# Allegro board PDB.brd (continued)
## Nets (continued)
GND: C1.2(B) C2.2(B) C3.2(B) C4.2(B) C5.2(B) C6.2(B) C7.2(B) C8.2(B) C9.2(B) C10.2(B) C11.2(B) C12.2(B) C13.2(B) C14.2(B) C15.2(B) C16.2(B) C17.2(B) C18.2(B) C19.2(B) C20.2(B) C21.2(B) C22.2(B) C23.2(B) C24.2(B) C25.2(B) C26.2(B) C27.2(B) C28.2(B) C29.2(B) C30.2(B) C31.2(B) C32.2(B) C33.2(B) C34.2(B) C35.2(B) C36.2(B) C39.2(B) C40.2(B) C41.2(B) C42.2(B) C43.1 C44.1 C45.2(B) C46.2(B) C47.2(B) C48.2(B) C49.2(B) C50.2(B) C51.2(B) C52.2(B) C53.1 C54.1 C55.2(B) C56.2(B) C57.2(B) C58.2(B) C59.2(B) C60.2(B) C61.2(B) C62.2(B) C63.2(B) C64.2(B) C65.2(B) C66.2(B) C67.2(B) C68.2(B) C69.2(B) C70.2(B) C71.2(B) C72.2(B) C73.2(B) C74.2(B) C75.2(B) C76.2(B) C77.2(B) C78.2(B) C79.2(B) C80.2(B) C81.2(B) C82.2(B) C83.2(B) C84.2(B) C85.2(B) C86.2(B) C87.2(B) C88.2(B) C89.2(B) C90.2(B) C91.2(B) C92.2(B) C97.2(B) C98.2(B) C99.2(B) C100.2(B) C101.2(B) C102.2(B) C103.2(B) C104.2(B) C105.2(B) C108.2(B) C109.2(B) C114.2(B) C115.2(B) C116.2(B) C117.2(B) C118.2(B) C119.2(B) C120.2(B) C121.2(B) C122.2(B) C123.2(B) C124.2(B) C125.2(B) C126.2(B) C127.2(B) C128.2(B) C129.2(B) C130.2(B) C131.2(B) C132.2(B) C133.2(B) C134.2(B) C135.2(B) C136.2(B) C137.2(B) C138.2(B) C139.2(B) C140.2(B) C141.2(B) C142.2(B) C143.2(B) C144.2(B) C145.2(B) C146.2(B) C147.2(B) C148.2(B) C149.2(B) C150.2(B) C151.2(B) C152.2(B) C153.2(B) C154.2(B) C155.2(B) C156.2(B) C157.2(B) C158.2(B) C159.2(B) C160.2(B) C161.2(B) C162.2(B) C163.2(B) C164.2(B) C165.2(B) C166.2(B) C167.2(B) C168.2(B) C170.2(B) C171.2(B) C172.2(B) C174.2(B) C175.2(B) C176.2(B) C178.2(B) C191.2(B) C192.2(B) C193.2(B) D7.1 D7.2 D8.1 D8.2 D9.1 D9.2 D10.1 D10.2 D11.2 J1.7 J1.8 J1.9 J1.10 J1.11 J1.12 J1.19 J1.20 J1.21 J1.22 J1.23 J1.24 J2.7 J2.8 J2.9 J2.10 J2.11 J2.12 J2.19 J2.20 J2.21 J2.22 J2.23 J2.24 J3.7 J3.8 J3.9 J3.10 J3.11 J3.12 J3.19 J3.20 J3.21 J3.22 J3.23 J3.24 J4.7 J4.8 J4.9 J4.10 J4.11 J4.12 J4.19 J4.20 J4.21 J4.22 J4.23 J4.24 J5.9 J6.9 J7.9 J8.9 J9.3 J9.8 J10.2 J11.1 J11.2 J11.3 J11.4 J11.5 J11.6 J11.13 J11.14(GND2) J12.2 J12.3 J12.6 J12.7 J13.1 J13.2 J13.3 J13.4 J13.9 J13.10 J13.11 J13.12 J13.17 J13.18(GND2) J14.1 J14.2 J14.3 J14.4 J14.9 J14.10 J14.11 J14.12 J14.17 J14.18(GND2) J15.1 J15.2 J15.3 J15.4 J15.9 J15.10 J15.11 J15.12 J15.17 J15.18(GND2) J16.7 J16.8 J16.9 J16.10 J16.11 J16.12 J16.13 J16.14(GND2) J17.7 J17.8 J17.9 J17.10 J17.11 J17.12 J17.13 J17.14(GND2) J18.7 J18.8 J18.9 J18.10 J18.11 J18.12 J18.13 J18.14(GND2) J19.1 J19.3 J19.5 J19.6(GND2) J20.2 MH1.2 MH1.3 MH1.4 MH1.5 MH1.6 MH2.2 MH2.3 MH2.4 MH2.5 MH2.6 MH3.2 MH3.3 MH3.4 MH3.5 MH3.6 MH4.2 MH4.3 MH4.4 MH4.5 MH4.6 MH5.2 MH5.3 MH5.4 MH5.5 MH5.6 MH6.1 MH7.1 PC29.2(B) PC30.2(B) PC31.2(B) PC32.2(B) PC33.2(B) PC34.2(B) PC101.2(B) PC102.2(B) PC103.2(B) PC104.2(B) PC105.2(B) PC106.2(B) PC107.2(B) PC108.2(B) PC819.2(B) PC820.2(B) PC822.2(B) PC824.2(B) PC825.2(B) PC827.2(B) PC830.2(B) PC832.2(B) PC833.2(B) PC834.2(B) PC835.2(B) PC836.2(B) PC837.2(B) PC838.2(B) PC840.2(B) PC841.2(B) PC843.2(B) PC844.2(B) PC845.2(B) PC846.2(B) PC847.2(B) PC848.2(B) PC849.2(B) PC850.2(B) PC851.2(B) PC1021.1 PC1022.2(B) PC1024.2(B) PC1819.2(B) PC1820.2(B) PC1822.2(B) PC1824.2(B) PC1825.2(B) PC1827.2(B) PC1830.2(B) PC1832.2(B) PC1833.2(B) PC1834.2(B) PC1835.2(B) PC1836.2(B) PC1837.2(B) PC1838.2(B) PC1840.2(B) PC1841.2(B) PC1843.2(B) PC1844.2(B) PC1845.2(B) PC1846.2(B) PC1847.2(B) PC1848.2(B) PC1849.2(B) PC1850.2(B) PC1851.2(B) PD1.2 PQ2.1 PQ2.4 PR24.2(B) PR707.2(B) PR1040.2(B) PR1046.1 PR1707.2(B) PU12.23 PU33.11 PU113.11 Q1.1 Q1.4 Q2.1 Q2.4 Q3.S Q4.S Q13.1 Q13.4 Q14.1 Q14.4 Q15.1 Q15.4 Q16.1 Q16.4 Q17.1 Q17.4 Q18.1 Q18.4 Q19.1 Q19.4 Q20.1 Q20.4 Q21.1 Q21.4 Q22.1 Q22.4 R17.2(B) R18.2(B) R19.2(B) R20.2(B) R26.2(B) R27.2(B) R28.2(B) R29.2(B) R30.2(B) R31.2(B) R32.2(B) R33.2(B) R34.2(B) R35.2(B) R47.2(B) R61.2(B) R78.2(B) R80.2(B) R82.2(B) R84.2(B) R86.2(B) R88.2(B) R117.2(B) R119.2(B) R121.2(B) R123.2(B) R125.2(B) R127.2(B) R129.2(B) R136.2(B) R137.2(B) R138.2(B) R141.2(B) R143.2(B) R150.2(B) R151.2(B) R153.2(B) R156.2(B) R158.2(B) R163.2(B) R166.2(B) R167.2(B) R173.2(B) R181.2(B) R197.2(B) R199.2(B) R212.2(B) SHORT2.2 U1.12(VSS) U2.6 U3.4 U4.2 U5.2 U6.2 U7.2 U8.2 U9.2 U10.2 U11.2 U12.3 U13.4 U14.8(VSS) U15.4 U16.4 U17.4 U18.4 U19.4 U20.2 U21.3 U22.3 U23.3
P3V3_CB: D6.A J12.4 J12.8 PR1705.1 PSHORT15.2 PSHORT61.2 PSHORT71.2
P3V3_CB_AGND: PC1823.2(B) PR1706.2(B) PR1707.1 PR1711.1 PR1712.1 PU113.4 PU113.17
P3V3_CB_COMP: PC1829.1 PR1710.1 PU113.3
P3V3_CB_COMP_RC: PC1831.1 PR1710.2(B)
P3V3_CB_EN: PC1819.1 PU113.15 R15.2(B) R197.1 R198.2(B)
P3V3_CB_FB: PC1829.2(B) PC1831.2(B) PR1712.2(B) PR1716.1 PR1717.1 PU113.1
P3V3_CB_FB_RC: PC1842.1 PR1716.2(B)
P3V3_CB_OUT: PC1834.1 PC1835.1 PC1837.1 PC1838.1 PC1840.1 PC1841.1 PC1844.1 PC1845.1 PC1847.1 PC1848.1 PC1850.1 PL126.2 PR1714.2(B) PR1719.2(B) PSHORT15.1 PSHORT61.1 PSHORT71.1
P3V3_CB_PG: PC1820.1 PR1705.2(B) PU113.7 Q4.G
P3V3_CB_RT: PR1706.1 PU113.5
P3V3_CB_S_VCC: PC1822.1 PU113.6 PU113.10
P3V3_CB_SENSE_R: PC1842.2(B) PR1717.2(B) PR1719.1
P3V3_CB_VIN: PC1824.1 PR1708.2(B) PU113.9
P3V3_CB_VREF: PC1823.1 PU113.2
P3V3_CB_VSNS: PR1711.2(B) PR1714.1 PU113.8(VSNS)
P3V3_RISER4: C90.1 C91.1 C92.1 J19.4 PC30.1 PC31.1 PC32.1 PC33.1 PQ3.1 PQ3.2 PQ3.3 R138.1
P3V3_STBY: C16.1 C26.1 C28.1 C33.1 C34.1 C35.1 C36.1 C61.1 C97.1 C98.1 C99.1 C100.1 C101.1 C102.1 C103.1 C104.1 C114.1 C115.1 D1.A L33.2 PC29.1 PQ3.5 PR27.1 PR705.1 PR10152.1 PR10153.1 PR10154.1 PSHORT5.2 PSHORT6.2 PSHORT7.2 R7.1 R8.1 R9.1 R10.1 R21.2(B) R22.2(B) R23.2(B) R24.2(B) R25.1 R36.1 R37.1 R38.1 R39.1 R46.1 R59.1 R60.1 R62.1 R63.1 R64.1 R77.1 R79.1 R81.1 R83.1 R85.1 R87.1 R93.1 R94.1 R95.1 R96.1 R97.1 R98.1 R99.1 R100.1 R101.1 R102.1 R103.1 R104.1 R105.1 R106.1 R107.1 R108.1 R109.1 R110.1 R111.1 R112.1 R118.1 R120.1 R122.1 R124.1 R165.1 R168.1 R185.1 R188.1 U1.24 U2.1(VDD) U3.8 U4.5 U5.5 U6.5 U7.5 U8.5 U9.5 U10.5 U11.5 U12.5 U13.8 U14.16 U19.8 U21.5 U22.5 U23.5
P3V3_STBY_AGND: PC823.2(B) PR706.2(B) PR707.1 PR711.1 PR712.1 PU33.4 PU33.17
P3V3_STBY_COMP: PC829.1 PR710.1 PU33.3
P3V3_STBY_COMP_RC: PC831.1 PR710.2(B)
P3V3_STBY_EN: PC819.1 PR702.2(B) PU33.15 R199.1 R200.2(B)
P3V3_STBY_FB: PC829.2(B) PC831.2(B) PR712.2(B) PR716.1 PR717.1 PU33.1
P3V3_STBY_FB_RC: PC842.1 PR716.2(B)
P3V3_STBY_OUT: PC834.1 PC835.1 PC837.1 PC838.1 PC840.1 PC841.1 PC844.1 PC845.1 PC847.1 PC848.1 PC850.1 PL26.2 PR714.2(B) PR719.2(B) PSHORT5.1 PSHORT6.1 PSHORT7.1
P3V3_STBY_PG_R: PC820.1 PR704.2(B) PR705.2(B) PU33.7
P3V3_STBY_PWRGD: PR704.1 R16.1
P3V3_STBY_PWRGD_R: R16.2(B) U12.1
P3V3_STBY_RT: PR706.1 PU33.5
P3V3_STBY_S_VCC: PC822.1 PU33.6 PU33.10
P3V3_STBY_SENSE_R: PC842.2(B) PR717.2(B) PR719.1
P3V3_STBY_VIN: PC824.1 PR708.2(B) PU33.9
P3V3_STBY_VREF: PC823.1 PU33.2
P3V3_STBY_VSNS: PR711.2(B) PR714.1 PU33.8(VSNS)
P12V_FAN: C20.1 C22.1 C24.1 C52.1 C64.1 C96.2(B) C159.1 J11.7 J11.8 J11.9 J11.10 J11.11 J11.12 PU17.2(B) R242.1 U18.7
P12V_PSU: C1.1 C2.1 C3.1 C4.1 C5.1 C6.1 C7.1 C8.1 C9.1 C10.1 C11.1 C12.1 C13.1 C14.1 C15.1 C17.1 C18.1 C77.1 C78.1 C79.1 C80.1 C81.1 C82.1 C83.1 C153.1 C154.1 C155.1 C156.1 C157.1 D11.1 J1.1 J1.2 J1.3 J1.4 J1.5 J1.6 J1.13 J1.14 J1.15 J1.16 J1.17 J1.18 J2.1 J2.2 J2.3 J2.4 J2.5 J2.6 J2.13 J2.14 J2.15 J2.16 J2.17 J2.18 J3.1 J3.2 J3.3 J3.4 J3.5 J3.6 J3.13 J3.14 J3.15 J3.16 J3.17 J3.18 J4.1 J4.2 J4.3 J4.4 J4.5 J4.6 J4.13 J4.14 J4.15 J4.16 J4.17 J4.18 PD1.1 PR23.1 PR1011.1 PR1015.2(B) PR1016.2(B) PR1017.2(B) PR1018.2(B) PR1019.2(B) PR1020.2(B) PR1034.1 PR1038.1 PR1039.1 PU18.1 PU19.1 PU20.1 PU21.1 PU22.1 PU23.1 R48.1 R58.2(B) R152.1 R154.1 R157.1 R189.1 R234.1 R236.1 R238.1 R240.1 SHORT1.2
P12V_RISER3: C65.1 C66.1 C67.1 C68.1 C84.1 C160.1 C163.1 J13.5 J13.6 J13.7 J13.8 J13.13 J13.14 J13.15 J13.16 J16.1 J16.2 J16.3 J16.4 J16.5 PU10.2(B) PU11.2(B) R204.1 R205.1 R221.1 R235.1
P12V_RISER4: C72.1 C74.1 C75.1 C76.1 C85.1 C86.1 C88.1 C89.1 C161.1 C164.1 J14.5 J14.6 J14.7 J14.8 J14.13 J14.14 J14.15 J14.16 J17.1 J17.2 J17.3 J17.4 J17.5 J19.2 PU13.2(B) PU14.2(B) R57.1 R206.1 R207.1 R222.1 R239.1
P12V_RISER5: C69.1 C70.1 C71.1 C73.1 C87.1 C162.1 C165.1 J15.5 J15.6 J15.7 J15.8 J15.13 J15.14 J15.15 J15.16 J18.1 J18.2 J18.3 J18.4 J18.5 PU15.2(B) PU16.2(B) R210.1 R211.1 R223.1 R243.1
P12V_STBY: C117.1 C118.1 C119.1 C120.1 C121.1 C122.1 C123.1 C124.1 C125.1 C126.1 C127.1 D8.3(CATHOD) J16.6 J17.6 J18.6 PC851.1 PC1851.1 PL28.2 PL128.2 PR708.1 PR1708.1 Q5.1 Q5.2 Q5.3 R171.1 R180.1 R200.1
P12V_SW_PSU: C19.1 C21.1 C23.1 C50.1 C63.1 C96.1 C158.1 D7.3(CATHOD) D9.3(CATHOD) D10.3(CATHOD) J12.1 J12.5 PC101.1 PC102.1 PC103.1 PC104.1 PC105.1 PC106.1 PC107.1 PC108.1 PC1024.1 PQ101.1 PQ101.2 PQ101.3(S3) PQ102.1 PQ102.2 PQ102.3(S3) PQ103.1 PQ103.2 PQ103.3(S3) PQ104.1 PQ104.2 PQ104.3(S3) PQ105.1 PQ105.2 PQ105.3(S3) PQ106.1 PQ106.2 PQ106.3(S3) PQ107.1 PQ107.2 PQ107.3(S3) PQ108.1 PQ108.2 PQ108.3(S3) PR25.1 PR1045.1 PR1048.1 PU10.1 PU11.1 PU13.1 PU14.1 PU15.1 PU16.1 PU17.1 R125.1 R182.2(B) R198.1 R201.2(B) R202.2(B) R203.2(B) R208.2(B) R209.2(B) R244.1 U18.8
ADM1278_ADR1: PU12.7 R11.2(B)
ADM1278_ADR2: PU12.8 R12.1
AT24C64_ADD0: R118.2(B) R119.1 U3.1
AT24C64_ADD1: R120.2(B) R121.1 U3.2
AT24C64_ADD2: R122.2(B) R123.1 U3.3
BMC_NODE_ID_0: C134.1 J5.3 L2.1
BMC_NODE_ID_0_R: J8.3 L2.2
BMC_NODE_ID_1: C145.1 J5.4 L12.2
BMC_NODE_ID_1_R: J8.4 L12.1
BMC_NODE_ID_2: C139.1 J5.14 L16.2
BMC_NODE_ID_2_R: J8.14 L16.1
BMC_NODE_ID_3: C129.1 J5.15 L6.1
BMC_NODE_ID_3_R: J8.15 L6.2
BMC_NODE_ID_4: C138.1 J5.16 L17.2
BMC_NODE_ID_4_R: J8.16 L17.1
BMC_NODE_ID_5: C128.1 J5.17 L7.1
BMC_NODE_ID_5_R: J8.17 L7.2
CSOUT_N: C60.1 R164.2(B) R167.1 U19.2
CSOUT_P: C59.1 R165.2(B) R166.1 U19.3
EMC1413_ADDR: R124.2(B) U2.7
EMC1413_ALERT_N: R46.2(B) U2.8
EN_HSC_IN: R183.1 R185.2(B) R212.1 U1.6
EN_HSC_IN_R: R183.2(B) U12.2
EN_HSC_P2V_IN_N: J20.1 Q19.5 Q19.6 R157.2(B) R158.1
EN_HSC_P12V_IN: PR1014.1 Q19.3 R13.2(B)
EN_HSC_P12V_IN_BUF: R184.1 U12.4(Y)
EN_HSC_P12V_IN_BUF_R1: Q19.2 R163.1 R184.2(B)
EN_HSC_P12V_STBY: C107.1 R152.2(B) R153.1 U20.4
EN_P3V3_D1G2: PQ2.5 PQ2.6 PR23.2(B) PR24.1
EN_P3V3_D2: PQ2.3 PR25.2(B) PR26.1
EN_P3V3_G1: PQ2.2 PR22.2(B)
EN_P3V3_GATE: PC28.2(B) PC34.1 PQ3.4 PR26.2(B)
FAN_OC_ALERT: Q16.5 R4.1 R29.1 R145.2(B) R147.1
FAN_OC_ALERT_N: Q2.6 R3.2(B)
FAN_OC_ALERT_R: Q2.2 Q2.5 R4.2(B)
FAN_OC_ALERT_R1_N: Q2.3 R6.1
FAN_OC_ALERT_R_N: R3.1 R10.2(B) U1.20
FAN_OC_CLEAR: Q16.2 R20.1 U1.11
HS_P12V_RSEN: PQ101.5_8 PQ102.5_8 PQ103.5_8 PQ104.5_8 PQ105.5_8 PQ106.5_8 PQ107.5_8 PQ108.5_8 PR1027.2(B) PR1028.2(B) PR1029.2(B) PR1030.2(B) PR1031.2(B) PR1032.2(B) PU18.2(B) PU19.2(B) PU20.2(B) PU21.2(B) PU22.2(B) PU23.2(B) R139.2(B) R189.2(B)
HSC_P12V_AGND: PC109.2(B) PC1010.2(B) PC1011.2(B) PC1012.2(B) PC1013.2(B) PC1014.2(B) PC1015.2(B) PC1016.2(B) PC1017.2(B) PC1018.2(B) PC1020.2(B) PC1023.2(B) PR109.2(B) PR1010.2(B) PR1013.2(B) PR1033.2(B) PR1036.2(B) PR1037.2(B) PR1040.1 PR1050.2(B) PU12.22 PU12.33(G) R12.2(B)
HSC_P12V_ALERT_N: PR10153.2(B) PU12.13
HSC_P12V_CSOUT: PU12.19 R164.1
HSC_P12V_DN: PC1020.1 PR1027.1 PR1028.1 PR1029.1 PR1030.1 PR1031.1 PR1032.1 PR1042.1 PU12.27 R139.1
HSC_P12V_DP: PC1018.1 PR1015.1 PR1016.1 PR1017.1 PR1018.1 PR1019.1 PR1020.1 PR1041.1 PU12.28 R58.1
HSC_P12V_EN: PC1011.1 PR1010.1 PR1011.2(B) PR1014.2(B) PU12.12
HSC_P12V_FAULT_N: PR10154.2(B) PU12.6 U1.15
HSC_P12V_GATE: PC1022.1 PR101.2(B) PR102.2(B) PR103.2(B) PR104.2(B) PR105.2(B) PR106.2(B) PR107.2(B) PR1049.2(B) PU12.24
HSC_P12V_GATE1: PQ101.4 PR102.1
HSC_P12V_GATE2: PQ102.4 PR103.1
HSC_P12V_GATE3: PQ103.4 PR104.1
HSC_P12V_GATE4: PQ104.4 PR105.1
HSC_P12V_GATE5: PQ105.4 PR106.1
HSC_P12V_GATE6: PQ106.4 PR101.1
HSC_P12V_GATE7: PQ107.4 PR1049.1
HSC_P12V_GATE8: PQ108.4 PR107.1
HSC_P12V_ISET: PC1014.1 PR1035.2(B) PR1036.1 PU12.3
HSC_P12V_ISTART: PC1010.1 PR108.2(B) PR109.1 PU12.4
HSC_P12V_MON: PC1019.2(B) PR1042.2(B) PU12.26
HSC_P12V_MOP: PC1019.1 PR1041.2(B) PU12.29
HSC_P12V_OV: PC1013.1 PR1033.1 PR1034.2(B) PU12.32
HSC_P12V_PSET: PC1012.1 PR1012.2(B) PR1013.1 PU12.1
HSC_P12V_PWGIN: PC1023.1 PR1048.2(B) PR1050.1 PU12.21
HSC_P12V_PWRGD: PR22.1 PR10152.2(B) Q3.G R14.2(B) R15.1
HSC_P12V_PWRGD_R: PU12.18 R14.1
HSC_P12V_STBY_AGND: C106.2(B) C107.2(B) R47.1
HSC_P12V_STBY_FAULT_INPUT: R180.2(B) R181.1 U20.6
HSC_P12V_STBY_GATE: Q5.4 R49.2(B) R50.1
HSC_P12V_STBY_GATE_R: R49.1 U20.5
HSC_P12V_STBY_PWRGD: C109.1 PR702.1 R171.2(B) R173.1 U20.3
HSC_P12V_STBY_RSENSE: Q5.5 R48.2(B) R155.1
HSC_P12V_STBY_TIMER: C106.1 U20.1
HSC_P12V_TEMP: PC1021.2(B) PR1047.1 PU12.25
HSC_P12V_TIMER: PC1016.1 PU12.5
HSC_P12V_UV: PC1015.1 PR1037.1 PR1038.2(B) PU12.31
HSC_P12V_VCAP: PC109.1 PR108.1 PR1012.1 PR1035.1 PU12.2 R11.1
HSC_P12V_VCC: PC1017.1 PR1039.2(B) PU12.30
HSC_P12V_VOUT: PR1045.2(B) PU12.20
I2C_ADM1278_SCL: PR1043.1 PU12.16
I2C_ADM1278_SDA: PR1044.1 PU12.15
I2C_BMC_MM3_R_SCL: J9.5 L9.2
I2C_BMC_MM3_R_SDA: J9.4 L19.1
I2C_BMC_MM3_SCL: C135.1 L9.1 R90.1 R104.2(B)
I2C_BMC_MM3_SDA: C140.1 L19.2 R89.1 R103.2(B)
I2C_BMC_MM8_R_SCL: J9.1 L8.2
I2C_BMC_MM8_R_SDA: J9.2 L18.1
I2C_BMC_MM8_SCL: C137.1 L8.1 PR1043.2(B) R92.1 R106.2(B) R113.1 R115.1
I2C_BMC_MM8_SDA: C142.1 L18.2 PR1044.2(B) R91.1 R105.2(B) R114.1 R116.1
I2C_FRU_SCL: R113.2(B) U3.6
I2C_FRU_SDA: R114.2(B) U3.5
I2C_MB_SCL: C131.1 L4.1 R51.1 R102.2(B)
I2C_MB_SCL_R: J8.7 L4.2
I2C_MB_SDA: C143.1 L14.2 R54.2(B) R101.2(B)
I2C_MB_SDA_R: J8.8 L14.1
I2C_PCA9546A_SCL: R90.2(B) U14.14
I2C_PCA9546A_SDA: R89.2(B) U14.15
I2C_PCA9555_SCL: R92.2(B) U1.22
I2C_PCA9555_SDA: R91.2(B) U1.23
I2C_PSU1_SCL: J5.7 R51.2(B)
I2C_PSU1_SDA: J5.8 R54.1
I2C_PSU2_R_SCL: J6.7 R52.2(B)
I2C_PSU2_R_SDA: J6.8 R55.1
I2C_PSU2_SCL: R52.1 R94.2(B) U14.5
I2C_PSU2_SDA: R55.2(B) R93.2(B) U14.4
I2C_PSU3_R_SCL: J7.7 R53.2(B)
I2C_PSU3_R_SDA: J7.8 R56.1
I2C_PSU3_SCL: R53.1 R96.2(B) U14.7
I2C_PSU3_SDA: R56.2(B) R95.2(B) U14.6
I2C_TEMP_SENSOR_SCL: R115.2(B) U2.10
I2C_TEMP_SENSOR_SDA: R116.2(B) U2.9
INA301_P12V_RISER3_DN: C42.1 C94.2(B) R204.2(B) R205.2(B) U15.7
INA301_P12V_RISER3_DP: C40.1 C94.1 R182.1 R201.1 U15.8
INA301_P12V_RISER4_DN: C41.1 C93.2(B) R206.2(B) R207.2(B) U16.7
INA301_P12V_RISER4_DP: C39.1 C93.1 R202.1 R203.1 U16.8
INA301_P12V_RISER5_DN: C51.1 C95.2(B) R210.2(B) R211.2(B) U17.7
INA301_P12V_RISER5_DP: C49.1 C95.1 R208.1 R209.1 U17.8
LED_P3V3_CB_N: D6.C R45.2(B)
LED_P3V3_CB_R_N: Q4.D R45.1
LED_P3V3_STBY_N: D1.C R44.1
LED_P3V3_STBY_R_N: Q3.D R44.2(B)
NC_HSC_P12V_MCLK: PU12.10
NC_HSC_P12V_MDAT: PU12.11
NC_HSC_P12V_SPI: PU12.9
NC_MB_PIN18: J8.18
NC_P3V3_CB_VP: PU113.16
NC_P3V3_STBY_VP: PU33.16
NC_PSU1_PIN18: J5.18
NC_PSU2_LR_SELECT: J6.2
NC_PSU2_NODE_ID_0: J6.3
NC_PSU2_NODE_ID_1: J6.4
NC_PSU2_NODE_ID_2: J6.14
NC_PSU2_NODE_ID_3: J6.15
NC_PSU2_NODE_ID_4: J6.16
NC_PSU2_NODE_ID_5: J6.17
NC_PSU2_PIN18: J6.18
NC_PSU2_THROTTLE_R: J6.5
NC_PSU3_LR_SELECT: J7.2
NC_PSU3_NODE_ID_0: J7.3
NC_PSU3_NODE_ID_1: J7.4
NC_PSU3_NODE_ID_2: J7.14
NC_PSU3_NODE_ID_3: J7.15
NC_PSU3_NODE_ID_4: J7.16
NC_PSU3_NODE_ID_5: J7.17
NC_PSU3_PIN18: J7.18
NC_PSU3_THROTTLE_R: J7.5
NC_PSU_GREEN_LED: J8.12
NC_PSU_YELLOW_LED: J8.13
OC1_ALERT_N: Q13.3 R126.2(B) U4.1 U15.6
OC1_DELAY: R40.2(B) R134.1 U4.6
OC1_DELAY_N: U4.4 U5.1
OC1_DELAY_RC: C47.1 D2.1 R134.2(B) U4.3
OC1_DELAY_RD: D2.3 R40.1
OC1_LIMIT: R127.1 U15.3
OC1_OUT: C45.1 U15.2
OC1_RESET: Q13.6 R36.2(B) R130.1 U15.5
OC1_VS_R: C43.2(B) R21.1 R126.1 U15.1(VS)
OC2_ALERT_N: Q14.3 R128.2(B) U6.1 U16.6
OC2_DELAY: R41.2(B) R135.1 U6.6
OC2_DELAY_N: U6.4 U7.1
OC2_DELAY_RC: C48.1 D3.1 R135.2(B) U6.3
OC2_DELAY_RD: D3.3 R41.1
OC2_LIMIT: R129.1 U16.3
OC2_OUT: C46.1 U16.2
OC2_RESET: Q14.6 R37.2(B) R131.1 U16.5
OC2_VS_R: C44.2(B) R22.1 R128.1 U16.1(VS)
OC3_ALERT_N: Q15.3 R140.2(B) U8.1 U17.6
OC3_DELAY: R42.2(B) R148.1 U8.6
OC3_DELAY_N: U8.4 U9.1
OC3_DELAY_RC: C57.1 D4.1 R148.2(B) U8.3
OC3_DELAY_RD: D4.3 R42.1
OC3_LIMIT: R141.1 U17.3
OC3_OUT: C55.1 U17.2
OC3_RESET: Q15.6 R38.2(B) R144.1 U17.5
OC3_VS_R: C53.2(B) R23.1 R140.1 U17.1(VS)
OC4_ALERT_N: Q16.3 R142.2(B) U10.1 U18.6
OC4_DELAY: R43.2(B) R149.1 U10.6
OC4_DELAY_N: U10.4 U11.1
OC4_DELAY_RC: C58.1 D5.1 R149.2(B) U10.3
OC4_DELAY_RD: D5.3 R43.1
OC4_LIMIT: R143.1 U18.3
OC4_OUT: C56.1 U18.2
OC4_RESET: Q16.6 R39.2(B) R145.1 U18.5
OC4_VS_R: C54.2(B) R24.1 R142.1 U18.1(VS)
OC_ALERT_N: R5.2(B) R6.2(B) R13.1 R25.2(B) R170.2(B) R172.2(B)
PCA9546A_ADD0: R85.2(B) R86.1 U14.1
PCA9546A_ADD1: R81.2(B) R82.1 U14.2
PCA9546A_ADD2: R77.2(B) R78.1 U14.13
PCA9555_ADD0: R87.2(B) R88.1 U1.21
PCA9555_ADD1: R83.2(B) R84.1 U1.2
PCA9555_ADD2: R79.2(B) R80.1 U1.3
PD_HEADER: CON1.3 R61.1
PD_LM393: R156.1 U19.5 U19.6
PDB_CURRENT_ALERT_N: R169.2(B) U1.16
PDB_CURRENT_ALERT_R_N: R168.2(B) R169.1 U19.1
PSU1_ALERT_BUF_N: R68.1 U21.4(Y)
PSU1_ALERT_N: J5.11 R62.2(B) U21.2
PSU1_BLADE_EN_N: J5.1 R72.1
PSU1_BLADE_EN_R1_N: J8.1 L1.2
PSU1_BLADE_EN_R_N: C32.1 C136.1 L1.1 R72.2(B) R110.2(B)
PSU1_GREEN_LED: J5.12 Q20.5 R33.1
PSU1_GREEN_LED_N: C152.1 L24.2 R177.2(B)
PSU1_GREEN_LED_R1_N: J10.4 L24.1
PSU1_GREEN_LED_R_N: Q20.3 R177.1
PSU1_LR_SELECT: C146.1 J5.2 L11.2
PSU1_LR_SELECT_R: J8.2 L11.1
PSU1_PRESENT_N: J5.6 R65.1
PSU1_PS_ON_N: J5.10 R69.2(B)
PSU1_THROTTLE_R: C132.1 J5.5 L3.1
PSU1_THROTTLE_R1: J8.5 L3.2
PSU1_VSENSE_DN: C111.2(B) J21.2 R192.1
PSU1_VSENSE_DP: C111.1 J21.1 R191.1
PSU1_YELLOW_LED: J5.13 Q20.2 R30.1
PSU1_YELLOW_LED_N: C147.1 L21.1 R174.1
PSU1_YELLOW_LED_R1_N: J10.3 L21.2
PSU1_YELLOW_LED_R_N: Q20.6 R174.2(B)
PSU2_ALERT_BUF_N: R186.1 U22.4(Y)
PSU2_ALERT_N: J6.11 R63.2(B) U22.2
PSU2_ALERT_R_N: J9.7 L10.2
PSU2_BLADE_EN_N: J6.1 R73.1
PSU2_BLADE_EN_R_N: C31.1 R73.2(B) R111.2(B) U1.13
PSU2_CPLD_PS_ON_N: C25.1 CON1.1 L20.2 R59.2(B)
PSU2_CPLD_PS_ON_R_N: J9.6 L20.1
PSU2_GREEN_LED: J6.12 Q21.5 R34.1
PSU2_GREEN_LED_N: C151.1 L25.2 R178.2(B)
PSU2_GREEN_LED_R1_N: J10.6 L25.1
PSU2_GREEN_LED_R_N: Q21.3 R178.1
PSU2_PRESENT_N: J6.6 R66.1
PSU2_PS_ON_BUF_N: R107.2(B) U1.4 U13.2
PSU2_PS_ON_N: J6.10 R70.2(B) R75.2(B)
PSU2_PS_ON_R_N: R75.1 U13.7
PSU2_VSENSE_DN: C112.2(B) J21.4 R194.1
PSU2_VSENSE_DP: C112.1 J21.3 R193.1
PSU2_YELLOW_LED: J6.13 Q21.2 R31.1
PSU2_YELLOW_LED_N: C148.1 L22.1 R175.1
PSU2_YELLOW_LED_R1_N: J10.5 L22.2
PSU2_YELLOW_LED_R_N: Q21.6 R175.2(B)
PSU3_ALERT_BUF_N: R187.1 U23.4(Y)
PSU3_ALERT_N: J7.11 R64.2(B) U23.2
PSU3_BLADE_EN_N: J7.1 R74.1
PSU3_BLADE_EN_R_N: C30.1 R74.2(B) R112.2(B) U1.14
PSU3_GREEN_LED: J7.12 Q22.5 R35.1
PSU3_GREEN_LED_N: C150.1 L26.2 R179.2(B)
PSU3_GREEN_LED_R1_N: J10.8 L26.1
PSU3_GREEN_LED_R_N: Q22.3 R179.1
PSU3_PRESENT_N: J7.6 R67.1
PSU3_PS_ON_BUF_N: R108.2(B) U1.5 U13.5
PSU3_PS_ON_N: J7.10 R71.2(B) R76.2(B)
PSU3_PS_ON_R_N: R76.1 U13.3(2Y)
PSU3_VSENSE_DN: C113.2(B) J21.6 R196.1
PSU3_VSENSE_DP: C113.1 J21.5 R195.1
PSU3_YELLOW_LED: J7.13 Q22.2 R32.1
PSU3_YELLOW_LED_N: C149.1 L23.1 R176.1
PSU3_YELLOW_LED_R1_N: J10.7 L23.2
PSU3_YELLOW_LED_R_N: Q22.6 R176.2(B)
PSU_ALERT_N: C116.1 C130.1 C133.1 L5.1 L10.1 R68.2(B) R186.2(B) R187.2(B) R188.2(B)
PSU_ALERT_R_N: J8.11 L5.2
PSU_PRESENT_N: C27.1 C144.1 L13.2 R65.2(B) R66.2(B) R67.2(B)
PSU_PRESENT_R_N: J8.6 L13.1
PSU_PS_ON_AND_N: CON1.2 R60.2(B) U13.1 U13.6
PSU_PS_ON_N: C29.1 C141.1 L15.2 R69.1 R70.1 R71.1
PSU_PS_ON_R1_N: J8.10 L15.1
PSU_VSENSE_DN: R192.2(B) R194.2(B) R196.2(B) SHORT2.1
PSU_VSENSE_DP: R191.2(B) R193.2(B) R195.2(B) SHORT1.1
PU_I2C_PCA9546A_2_SCL: R98.2(B) U14.10
PU_I2C_PCA9546A_2_SDA: R97.2(B) U14.9
PU_I2C_PCA9546A_3_SCL: R100.2(B) U14.12
PU_I2C_PCA9546A_3_SDA: R99.2(B) U14.11
RISER3_OC_ALERT: Q13.5 R26.1 R130.2(B) R132.1 R160.1
RISER3_OC_ALERT_N: Q17.6 R159.2(B)
RISER3_OC_ALERT_R: Q17.2 Q17.5 R160.2(B)
RISER3_OC_ALERT_R1_N: Q17.3 R170.1
RISER3_OC_ALERT_R_N: R7.2(B) R159.1 U1.17
RISER3_OC_CLEAR: Q13.2 R17.1 U1.8
RISER4_OC_ALERT: Q14.5 R27.1 R131.2(B) R133.1 R162.1
RISER4_OC_ALERT_N: Q18.6 R161.2(B)
RISER4_OC_ALERT_R: Q18.2 Q18.5 R162.2(B)
RISER4_OC_ALERT_R1_N: Q18.3 R172.1
RISER4_OC_ALERT_R_N: R8.2(B) R161.1 U1.18
RISER4_OC_CLEAR: Q14.2 R18.1 U1.9
RISER5_OC_ALERT: Q15.5 R2.1 R28.1 R144.2(B) R146.1
RISER5_OC_ALERT_N: Q1.6 R1.2(B)
RISER5_OC_ALERT_R: Q1.2 Q1.5 R2.2(B)
RISER5_OC_ALERT_R1_N: Q1.3 R5.1
RISER5_OC_ALERT_R_N: R1.1 R9.2(B) U1.19
RISER5_OC_CLEAR: Q15.2 R19.1 U1.10
RST_I2C_MUX_N: R109.2(B) U1.7 U14.3
TEMP_SENSE_1_DN: C38.2(B) Q11.2(E) U2.3
TEMP_SENSE_1_DP: C38.1 Q11.1 Q11.3 U2.2
TEMP_SENSE_2_DN: C37.2(B) Q10.2(E) U2.5
TEMP_SENSE_2_DP: C37.1 Q10.1 Q10.3 U2.4
TP_HSC_P12V_ALERT2: PU12.14
UNNAMED_9_AT24C64D_I33_WP: R117.1 U3.7(WP)
UNNAMED_10_RES_I2_A: R136.1 U5.3
UNNAMED_10_RES_I18_B: R132.2(B) U5.6
UNNAMED_10_RES_I30_A: R137.1 U7.3
UNNAMED_10_RES_I40_B: R133.2(B) U7.6
UNNAMED_11_RES_I2_A: R150.1 U9.3
UNNAMED_11_RES_I13_B: R146.2(B) U9.6
UNNAMED_11_RES_I20_A: R151.1 U11.3
UNNAMED_11_RES_I26_B: R147.2(B) U11.6
UNNAMED_12_NPN_I60_B: PQ109.1 PQ109.3 PR1047.2(B)
UNNAMED_12_NPN_I60_E: PQ109.2(E) PR1046.2(B)
UNNAMED_14_BEAD_I89_1: C62.1 J10.1 L33.1
UNNAMED_19_CAP_I128_A: PC28.1 PR27.2(B)
UNNAMED_23_CAP_I5_A: C166.1 R234.2(B)
UNNAMED_23_CAP_I8_A: C168.1 R236.2(B)
UNNAMED_23_CAP_I12_A: C170.1 R238.2(B)
UNNAMED_23_CAP_I17_A: C176.1 R244.2(B)
UNNAMED_23_CAP_I20_A: C174.1 R242.2(B)
UNNAMED_23_CAP_I24_A: C172.1 R240.2(B)
UNNAMED_23_CAP_I32_A: C175.1 R243.2(B)
UNNAMED_23_CAP_I40_A: C171.1 R239.2(B)
UNNAMED_23_CAP_I48_A: C167.1 R235.2(B)
UNNAMED_23_CAP_I52_A: C178.1 R57.2(B)
UNNAMED_23_CAP_I56_A: C191.1 R221.2(B)
UNNAMED_23_CAP_I60_A: C192.1 R222.2(B)
UNNAMED_23_CAP_I64_A: C193.1 R223.2(B)
UNNAMED_214_ADM1172_I37_SENSE: C110.2(B) R155.2(B) U20.7
UNNAMED_214_ADM1172_I37_VCC: C108.1 C110.1 R154.2(B) U20.8(VCC)
UNNAMED_214_CAP_I27_A: C105.1 R50.2(B)
VR_P3V3_CB_BT: PC1828.1 PU113.14
VR_P3V3_CB_PVIN: PC1825.1 PC1827.1 PC1830.1 PC1832.1 PC1833.1 PC1836.1 PC1843.1 PC1846.1 PC1849.1 PL128.1 PU113.13
VR_P3V3_CB_SW: PC1828.2(B) PL126.1 PU113.12
VR_P3V3_STBY_BT: PC828.1 PU33.14
VR_P3V3_STBY_PVIN: PC825.1 PC827.1 PC830.1 PC832.1 PC833.1 PC836.1 PC843.1 PC846.1 PC849.1 PL28.1 PU33.13
VR_P3V3_STBY_SW: PC828.2(B) PL26.1 PU33.12

Pads without a net: D2 2; D3 2; D4 2; D5 2; NOREF 1; NOREF#2 1; NOREF#3 1; NOREF#5 1; NOREF#6 1; NOREF#7 1; NOREF#8 1; NOREF#9 1; NOREF#10 1; PU12 17; U1 1; U5 4; U7 4; U9 4; U11 4; U19 7; U21 1; U22 1; U23 1

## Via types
v1: diameter 0.508, hole 0.254, TOP to BOTTOM, 1639 vias
v2: diameter 0.635, hole 0.318, TOP to BOTTOM, 70 vias
v3: diameter 0.762, hole 0.381, TOP to BOTTOM, 21 vias
v4: diameter 0.762, hole 0.254, TOP to BOTTOM, 10 vias

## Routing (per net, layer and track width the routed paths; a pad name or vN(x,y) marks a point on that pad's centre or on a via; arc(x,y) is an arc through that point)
GND: length 245.7
  TOP w0.254: v1(110.52,27.35) 110.81,27.05 PU12.23 ; SHORT2.2 27.6,61.62 27.73,61.75 27.73,62.12 27.6,62.24 C15.2 ; U2.6 96.33,100.56 96.18,100.71 96,100.71 v1(95.76,100.47) ; PC1820.2 172.57,111.91 v1(172.24,112.24)
  TOP w0.305: v1(110.52,27.35) 109.98,27.35 v1(109.88,27.45) 109.29,27.45 108.89,27.85 108.89,28.28 108.49,28.68 PC1021.1 107.48,28.68 PR1046.1 ; v1(174.04,102.85) 173.44,102.25 PC1819.2
  TOP w0.381: R181.2 108.13,7.56 v1(108.46,7.89) ; C116.2 v1(8.99,93.92) ; U13.4 v1(176.25,88.53) ; C164.2 v1(136.04,56.42) ; PQ2.1 169.04,33.27 168.91,33.4 v1(168.91,33.42) ; v1(147.17,35.71) 147.17,35.5 147.51,35.16 U12.3 ; C143.2 v1(11.81,91.44) ; v1(26.52,2.48) 26.82,2.48 27.01,2.29 Q22.4 ; v1(34.8,110.96) 34.61,110.77 U21.3 ; v1(70.61,29.86) 70.42,30.05 C31.2 ; v1(14.37,91.49) 14.37,91.45 14.35,91.44 C144.2 ; v1(69.34,31.89) 69.6,32.15 C157.2 ; R197.2 v1(174.12,101.23) ; v1(185,77.65) 185.06,77.59 R61.2 ; v1(16.76,10.05) 17.02,10.3 C150.2 C149.2 ; v1(32.94,5.2) 32.94,4.82 33.21,4.55 Q21.1 ; C148.2 C151.2 v1(18.54,9.64) ; C178.2 176.13,49.04 v1(176.17,49.09) ; C105.2 115.62,5.6 115.98,5.96 v1(115.98,6.72) ; C162.2 v1(165.21,87.28) ; v1(168.28,53.23) 168.4,53.1 C161.2 ; C9.2 78.11,88.28 v1(77.6,88.79) ; R32.2 R35.2 44.58,5.48 v1(44.32,5.73) ; v1(79.83,88.25) 79.88,88.2 C17.2 ; C75.2 v1(167.39,53.1) ; C128.2 v1(4.19,91.44) ; C147.2 C152.2 21.08,10.17 v1(21.34,9.92) ; PC824.2 158.7,13.97 PC820.2 157.23,13.58 v1(156.79,13.58) ; C64.2 v1(171.92,76.18) ; R173.2 C109.2 107.22,1.82 v1(107.44,2.05) ; C29.2 v1(27.94,107.58) ; C127.2 112.42,3.04 112.55,2.92 v1(112.55,2.86) ; C136.2 v1(20.7,91.44) 20.95,91.44 21.59,92.07 C32.2 ; PC34.2 v1(172.47,33.72) ; C70.2 v1(144.83,96.2) ; U22.3 v1(66.55,2.57) ; C33.2 v1(73.68,104.39) ; R212.2 151.15,35.07 v1(151.37,34.85) ; PQ2.4 167.24,34.57 v1(167.03,34.79) ; C145.2 v1(16.89,91.44) ; U20.2 104.5,2.94 R47.2 104.29,2.12 104.28,2.11 v1(104.28,1.91) ; C26.2 v1(29.19,110) ; v1(108.58,3.19) 108.15,3.62 R153.2 ; C175.2 v1(147.19,75.96) ; C24.2 v1(172.94,76.25) ; v1(39.67,108.93) 39.73,108.98 R30.2 ; Q22.1 v1(29.02,3.78) ; C25.2 v1(17.53,113.04) ; C34.2 v1(115.84,109.85) ; C133.2 v1(23.37,109.62) ; C62.2 v1(2.41,11.95) ; C71.2 C73.2 v1(143.13,94.76) ; C176.2 132.48,99.89 v1(132.66,99.71) ; C27.2 v1(17.88,93.87) ; C114.2 v1(70.74,3.85) ; C140.2 C135.2 v1(23.52,111.9) ; C155.2 v1(56.01,23) ; C129.2 v1(6.73,91.44) ; C171.2 v1(139.93,37.21) ; C146.2 v1(19.43,91.44) ; U14.8 82.54,110.09 82.88,110.43 82.88,110.83 v1(82.85,110.86) ; C138.2 v1(5.46,91.44) ; C141.2 v1(10.54,91.44) ; R84.2 R80.2 106.93,112.41 v1(106.3,111.77) ; PR24.2 v1(165.02,33.03) ; C165.2 v1(139.8,94.01) ; C16.2 v1(143.62,33.13) ; Q21.4 35.62,6.45 35.71,6.37 v1(35.76,6.37) ; C6.2 76.07,88.41 v1(75.76,88.72) ; R33.2 v1(39.67,110.63) ; R199.2 v1(157.1,27.32) ; C159.2 v1(165.23,59.07) ; C132.2 v1(15.62,91.44) ; C130.2 v1(9.27,91.44) ; C134.2 v1(18.16,91.44) ; C139.2 v1(8,91.44) ; C131.2 v1(13.34,91.44) ; C192.2 v1(158.67,53.1)
  TOP w0.457: PC1824.2 171.78,112.24 v1(172.24,112.24) ; v1(166.19,102.39) 166.19,102.58 PC1825.2 ; PC822.2 163.24,13.94 v1(163.97,13.94) ; v1(160.75,98.91) 160.32,98.91 PC1851.2 ; v1(163.99,23.53) 163.99,23.34 PC825.2 ; v1(166.26,111.81) PC1822.2
  TOP w0.508: U3.4 v1(169.01,96.04) ; v1(68.74,47.61) 69.47,46.88 C14.2 ; PC819.2 v1(156.51,23.61) ; C8.2 v1(26.29,64.02) ; R123.2 v1(170.92,94.77) ; C15.2 27.05,62.24 25.53,63.77 v1(25.53,64.15) ; C22.2 v1(170.43,77.1) ; U1.12 v1(106.43,101.64) ; C115.2 v1(116.33,1.54) ; C108.2 100.91,9.69 v1(100.76,9.84) ; R117.2 v1(158.85,93.5) ; v1(67.26,48.27) 67.69,47.84 C10.2 ; R119.2 v1(170.92,92.23) ; Q4.S v1(178.99,92.28) ; R121.2 v1(170.92,93.5) ; C13.2 v1(68.43,32.43) ; C166.2 v1(57.02,89.55) ; C28.2 v1(170.31,86.42) ; C5.2 60.82,32.47 v1(60.63,32.65) ; C11.2 v1(25.91,65.93) ; C23.2 v1(97.66,36.72) ; v1(60.91,30.55) 61.37,31 R31.2 ; C30.2 50.44,4.05 v1(50.72,3.77) ; C12.2 v1(65.79,32.47) ; C153.2 v1(26.9,87.77) ; C193.2 v1(172.09,85.23) ; C88.2 v1(164.53,53.16) ; C36.2 v1(158.88,92.23) ; R34.2 v1(65.74,31)
  BOTTOM w0.254: C57.2 139.09,96.36 U8.2 ; v1(138.45,92.23) 138.43,92.23 138.28,92.09 C101.2 ; C100.2 130.41,47.66 v1(130.56,47.51) ; R150.2 141.26,95.83 v1(141.26,95.07) ; v1(139.94,90.54) 140.04,90.44 C103.2 ; C58.2 178.73,79.9 U10.2 ; U6.2 v1(138.3,50.69)
  BOTTOM w0.305: U4.2 143.76,21.22 143.1,21.88 v1(143.1,22.21) ; v1(144.37,19.45) 144.53,19.6 145.41,19.6 C47.2 ; v1(144.37,19.45) 144.25,19.45 143.69,18.89 U5.2 ; v1(144.37,19.45) 144.46,19.36 144.46,18.71 R136.2 ; U11.2 180.9,82.74 v1(180.47,82.31) ; U9.2 141.43,94.43 141.26,94.6 v1(141.26,95.07) ; v1(181.03,78.91) 181.03,79.19 180.31,79.9 U10.2 ; v1(138.1,94.07) 138.38,94.07 139.09,94.78 U8.2 ; U7.2 135.2,48.43 135.45,48.67 v1(135.66,48.67)
  BOTTOM w0.381: v1(186.44,72.05) R143.2 186.33,72.78 U18.4 ; R129.2 139.22,54.02 v1(138.81,53.61) 138.68,53.48 R18.2 ; C49.2 v1(132.13,91.52) ; C55.2 136.4,99.33 v1(136.55,99.18) ; v1(180.15,76.95) 179.65,76.45 R20.2 ; v1(20.15,22.47) 20.17,22.47 21.03,23.33 C154.2 ; R17.2 144.78,25.38 v1(144.93,25.53) ; C43.1 v1(147.78,28.46) ; C56.2 v1(187.45,72.05) ; Q19.4 115.86,18.52 v1(115.77,18.42) ; R141.2 v1(136.55,98.31) ; PR1707.2 173.13,108.43 v1(173.13,108.22) ; v1(140.72,22.11) C97.2 ; v1(143.89,15.92) 143.9,15.9 Q17.4 ; v1(183.9,78.12) 184.02,78.25 C102.2 ; Q2.1 v1(186.2,84.83) ; v1(185.37,82.46) 185.37,81.75 185.12,81.5 C104.2 ; v1(157.99,13.1) 157.63,13.46 C191.2 ; C48.2 137.78,49.31 v1(137.67,49.42) ; C163.2 138.05,14.24 v1(138.3,14.49) ; R151.2 v1(181.23,85.74) ; v1(19.2,109) C142.2 C137.2 ; v1(133.26,51.83) 133.35,51.74 C98.2 ; v1(143.46,14.7) 143.38,14.7 143.29,14.6 Q17.1 ; R88.2 v1(111.76,109.74) ; v1(129.16,52.72) 129.43,52.99 R27.2 ; v1(110.19,2.61) 110.4,2.82 U23.3 ; v1(185.01,85.03) 185.01,85.04 184.9,85.15 Q2.4 ; v1(136.41,88.8) 136.43,88.79 R28.2 ; v1(26.48,64.93) 26.75,64.66 C156.2 ; C52.2 v1(177.45,73.22) ; C45.2 149,23.94 v1(148.77,23.71) ; v1(76.43,103.01) R82.2 R78.2 ; R137.2 v1(135.66,48.67) ; Q18.4 v1(127.45,47.78) ; v1(158.62,12.71) 158.73,12.61 C160.2 ; Q20.4 v1(18.22,98.76) ; R19.2 v1(136.02,96.89) ; Q20.1 v1(20.43,100.06) ; Q1.1 v1(144.02,88.9) ; R29.2 v1(187.83,79.9) ; C51.2 v1(132.33,88.95) ; v1(118.59,20.95) 118.09,20.45 Q19.1 116.99,21.15 R163.2 R158.2 ; C54.1 v1(185.55,76.75) ; C50.2 v1(177.29,75.8) ; C53.1 v1(130.3,97.93) ; R86.2 v1(82.57,102.91) ; C172.2 v1(56.13,23.89) ; v1(144.97,90.9) Q1.4 ; C61.2 v1(117.22,29.73) ; v1(92.08,103.27) C35.2
  BOTTOM w0.406: v1(143.1,22.21) 142.36,22.96 Q13.4 ; C46.2 v1(139.22,58.1) 139.09,58.23 C44.1 ; U17.4 134.78,97.2 135.01,97.44 135.52,97.44 135.86,97.78 135.86,98.29 R141.2 ; C42.2 v1(140.18,25.16) ; Q14.1 v1(135.16,54.5) ; v1(131.95,54.62) 131.55,55.03 C41.2 ; Q15.4 137.35,93.17 138.1,93.92 v1(138.1,94.07) ; v1(181.31,76.06) 181.31,76.57 181.02,76.86 Q16.1 ; C40.2 v1(140.84,28.43) ; v1(144.93,25.53) U15.4 146.8,25.53 147.75,24.58 R127.2 ; Q14.4 v1(133.26,51.83) ; Q13.1 v1(143.8,24.96) ; C39.2 v1(132.26,57.97) ; Q15.1 v1(135.46,94.26) ; U16.4 138.57,55.07 138.73,54.91 R129.2 ; Q16.4 181.93,78.16 181.18,78.91 v1(181.03,78.91)
  BOTTOM w0.432: Q18.1 v1(128.52,49.81)
  BOTTOM w0.508: PC1022.2 v1(104.9,26.68) ; C99.2 R26.2 v1(139.85,18.3) ; Q3.S v1(101.15,4.37) ; PR1040.2 110.52,27.09 v1(110.52,27.35) ; C170.2 v1(26.24,68.39) ; v1(156.46,17.46) 157.05,16.87 PR707.2 ; R156.2 v1(121.54,34.3) ; C168.2 v1(18.65,19.97) ; C174.2 v1(178.94,72.15) ; C167.2 v1(136.89,16.67)
  vias: v1(16.43,22.09) v1(16.36,21.33) v1(16.43,20.69) v1(19.18,17.92) v1(19.3,18.81) v1(25.4,78.88) v1(25.4,71.77) v1(25.53,76.6) v1(25.53,69.48) v1(26.54,78.88) v1(26.54,71.77) v1(26.67,76.6) v1(26.67,69.48) v1(51.56,64.53) v1(51.69,66.82) v1(52.32,27.32) v1(52.32,26.56) v1(52.32,25.8) v1(52.83,66.82) v1(53.09,64.53) v1(60.81,90.49) v1(61.52,90.49) v1(62.2,90.49) v1(63.37,48.15) v1(64.52,48.15) v1(65.53,64.53) v1(65.66,66.82) v1(66.29,47.77) v1(66.29,46.62) v1(66.8,66.82) v1(67.06,64.53) v1(70.33,90.49) v1(70.87,47.77) v1(70.87,46.62) v1(71.04,90.49) v1(71.73,90.49) v1(72.52,48.27) v1(72.64,64.53) v1(72.77,66.82) v1(73.15,35.57) v1(73.15,34.56) v1(73.15,33.42) v1(73.66,48.27) v1(73.91,66.82) v1(73.91,35.45) v1(73.91,34.05) v1(74.17,64.53) v1(74.93,51.45) v1(82.27,8.83) v1(83.01,8.73) v1(83.77,8.78) v1(91.17,34.48) v1(91.17,33.82) v1(91.17,33.16) v1(91.17,32.53) v1(97.41,33.92) v1(98.17,33.92) v1(102.74,94.88) v1(102.74,94.12) v1(102.74,93.23) v1(102.74,92.34) v1(102.87,28.97) v1(103.5,94.88) v1(103.5,94.12) v1(103.5,93.23) v1(103.5,92.34) v1(103.63,28.97) v1(103.63,28.21) v1(104.14,94.5) v1(104.14,93.49) v1(105.28,29.1) v1(105.92,29.1) v1(106.05,30.75) v1(106.05,29.86) v1(106.68,81.04) v1(106.68,80.38) v1(106.68,70.09) v1(106.68,69.43) v1(106.68,58.76) v1(106.68,58.1) v1(106.68,50.23) v1(106.68,49.57) v1(106.68,41.32) v1(106.68,40.65) v1(106.68,30.37) v1(106.68,29.35) v1(107.57,93.99) v1(107.57,93.23) v1(108.28,96.79) v1(108.33,95.29) v1(108.58,94.12) v1(108.58,93.36) v1(110.26,94.68) v1(110.57,94.02) v1(110.64,93.31) v1(110.77,81.02) v1(110.77,80.35) v1(110.77,70.07) v1(110.77,69.41) v1(110.77,58.76) v1(110.77,58.1) v1(110.77,50.21) v1(110.77,49.54) v1(110.77,41.29) v1(110.77,40.63) v1(111.05,94.73) v1(111.3,93.99) v1(111.38,93.28) v1(112.01,32.15) v1(113.03,32.15) v1(115.57,13.48) v1(115.57,12.71) v1(115.57,11.83) v1(116.33,13.22) v1(116.33,12.21) v1(116.33,11.19) v1(117.09,110.12) v1(117.09,109.23) v1(117.22,111.01) v1(119.63,13.54) v1(120.37,13.54) v1(121.07,13.54) v1(124.21,24.4) v1(125.6,76.21) v1(125.6,75.58) v1(127.89,76.21) v1(128.4,37.35) v1(128.65,98.06) v1(128.65,76.21) v1(129.67,37.35) v1(130.81,37.28) v1(131.95,97.3) v1(132.08,96.53) v1(132.08,95.01) v1(132.83,37.23) v1(137.54,61.23) v1(140.59,61.86) v1(140.97,29.22) v1(141.48,61.86) v1(142.11,61.1) v1(142.49,28.84) v1(142.72,28.03) v1(144.58,26.86) v1(144.65,27.88) v1(147.45,58.18) v1(147.45,57.42) v1(147.47,110.34) v1(147.47,108.1) v1(147.47,105.89) v1(148.13,110.34) v1(148.13,108.1) v1(148.18,105.89) v1(148.34,58.18) v1(148.34,57.42) v1(149.86,58.18) v1(149.99,60.09) v1(149.99,59.2) v1(150.7,97.12) v1(150.75,96.31) v1(151.45,27.7) v1(151.45,26.05) v1(151.45,25.11) v1(151.56,97.12) v1(152.65,15.38) v1(152.65,14.37) v1(153.57,17.41) v1(153.57,16.65) v1(154.76,94.63) v1(154.86,96.66) v1(155.12,101.83) v1(155.12,101.19) v1(155.62,103.4) v1(155.62,102.64) v1(155.6,100.64) v1(155.6,99.95) v1(157.53,111.51) v1(159.89,56.66) v1(160.25,104.78) v1(160.25,103.76) v1(160.72,24.9) v1(160.72,24.22) v1(160.72,22.82) v1(160.69,22.16) v1(160.77,56.59) v1(160.93,111.46) v1(161.4,56.64) v1(162.33,104.6) v1(162.33,103.96) v1(162.8,15.45) v1(163.18,14.94) v1(163.56,15.48) v1(163.8,100.17) v1(163.8,99.46) v1(163.94,14.97) v1(164.03,111.02) v1(164.35,15.48) v1(164.41,111.56) v1(164.72,110.97) v1(164.7,14.94) v1(164.75,16.04) v1(165.1,111.51) v1(165.07,110.41) v1(165.11,15.5) v1(165.09,14.41) v1(165.43,109.88) v1(165.48,110.97) v1(165.47,14.94) v1(165.84,110.44) v1(165.77,14.36) v1(166.02,23.94) v1(166.24,110.95) v1(166.15,14.89) v1(166.62,110.44) v1(166.76,23.94) v1(167,110.97) v1(167.38,110.47) v1(167.39,50.07) v1(167.75,23.94) v1(167.96,20.84) v1(168.49,23.94) v1(168.69,20.84) v1(169.34,103.1) v1(169.34,101.7) v1(169.34,101.02) v1(169.37,103.76) v1(169.73,20.35) v1(169.73,19.52) v1(170.69,33.67) v1(171.36,25.92) v1(171.44,21.8) v1(171.44,21.17) v1(171.58,33.67) v1(172.07,25.92) v1(172.47,47.64) v1(172.47,46.5) v1(173.23,48.53) v1(174.12,11.19) v1(174.12,10.43) v1(175.01,12.33) v1(176.46,18.25) v1(176.49,16.04) v1(176.66,83.71) v1(177.12,18.25) v1(177.16,83.07) v1(177.16,82.18) v1(177.18,16.04) v1(177.84,18.25) v1(177.84,16.04) v1(179.96,85.74) v1(180.38,48.55) v1(181.3,48.55) v1(182.5,48.66) v1(187.58,36.08) v1(187.58,35.19) v1(187.71,34.3) v1(187.71,33.54) v1(187.71,32.65) v1(187.71,31.64) v1(187.71,30.75)
P3V3_CB: length 48.9
  TOP w0.254: 146.2,112.37 146.87,113.04 172.8,113.04 173.53,112.31 PR1705.1 174.53,111.43 174.81,111.15 174.84,111.15 176.28,109.71 176.28,102.53 182.28,96.52 D6.A
P3V3_CB_AGND: length 6.1
  TOP w0.254: PR1706.2 171.97,107.96 v1(171.8,107.8) 171.72,107.71 PU113.4 v1(169.49,107.71)
  BOTTOM w0.254: v1(171.8,107.8) 172.48,107.8 172.95,107.33 172.95,106.13 PR1712.1
  vias: v2(169.65,106.75)
P3V3_CB_COMP: length 3.9
  TOP w0.254: PU113.3 171.95,107.21 172.04,107.3 172.72,107.3 PC1829.1 173.13,106.9 173.66,106.9 v1(173.69,106.92) 173.69,107.37 PR1710.1
P3V3_CB_COMP_RC: length 1.6
  TOP w0.305: PC1831.1 174.75,106.64 v1(175.01,106.9) 175.01,107.35 PR1710.2
P3V3_CB_EN: length 8.4
  TOP w0.216: PU113.15 169.49,105.29 170.24,104.54 171,104.54 171.24,104.54 171.53,104.25 171.53,104.02 171.53,103.3 v1(172.05,102.77) PC1819.1 R197.1 172.57,100.26 R198.2 R15.2
P3V3_CB_FB: length 7.1
  TOP w0.254: PR1716.1 172.5,105.26 PR1717.1 ; PR1716.1 172.48,105.73 PC1829.2 173,106.25 PC1831.2 ; PR1716.1 172.44,105.25 v1(171.78,105.25) 171.58,105.45 171.58,105.96 171.32,106.21 PU113.1
  BOTTOM w0.254: v1(171.78,105.25) 172.03,105 PR1712.2
P3V3_CB_FB_RC: length 1.6
  TOP w0.254: PC1842.1 173.01,103.88 v1(172.77,103.88) 172.48,104.17 PR1716.2
P3V3_CB_OUT: length 42.1
  BOTTOM w0.254: PR1719.2 148.76,101.32 147.84,101.32 146.43,102.73 146.43,112.68 147.12,113.37 172.34,113.37 172.92,112.78 172.92,110.89 PR1714.2
  vias: v1(149.25,110.36) v1(149.22,108.1) v1(149.2,105.87) v1(149.83,105.87) v1(149.88,110.36) v1(149.86,108.1) v1(150.24,101.83) v1(150.24,101.18) v1(150.88,101.83) v1(150.87,101.19) v2(151.82,105.91)
P3V3_CB_PG: length 21.7
  TOP w0.216: 171.88,110.64 171.32,110.08 171.32,109.41 171.13,109.21 PU113.7
  TOP w0.254: 171.88,110.64 PC1820.1 173.52,110.64 PR1705.2 173.55,110.65 174.62,110.65 175.82,109.45 175.82,102.34 178.99,99.17 v1(178.99,96.99) Q4.G
P3V3_CB_RT: length 1.9
  TOP w0.254: PR1706.1 171.97,108.76 171.42,108.21 PU113.5
P3V3_CB_S_VCC: length 8.5
  TOP w0.254: v1(168.25,110.83) 168.99,110.1 PU113.10 ; PU113.6 171.27,108.71 171.8,109.25 v1(171.8,109.86)
  TOP w0.305: PC1822.1 168.58,111.13 v1(168.25,110.83)
  VCC1 w0.381: v1(171.8,109.86) 171.79,109.87 169.21,109.87 v1(168.25,110.83)
P3V3_CB_SENSE_R: length 33.4
  TOP w0.254: v1(174.37,103.58) 174.23,103.72 PC1842.2 PR1717.2
  BOTTOM w0.254: v1(174.37,103.58) 174.75,103.21 174.75,100.07 172.74,98.06 149.71,98.06 148.79,98.97 PR1719.1
P3V3_CB_VIN: length 4.8
  TOP w0.254: v1(169.54,110.78) 169.49,110.59 PU113.9
  TOP w0.305: v1(169.54,110.78) 169.87,110.97 PC1824.1
  BOTTOM w0.305: v1(169.54,110.78) 169.32,110.78 PR1708.2
P3V3_CB_VREF: length 2.6
  TOP w0.254: v1(172.16,106.72) 172.06,106.72 172.06,106.72 170.77,106.72 PU113.2
  BOTTOM w0.254: v1(172.16,106.72) 171.95,106.93 PC1823.1
P3V3_CB_VSNS: length 4.6
  TOP w0.254: PU113.8 169.99,110.18 170.48,110.68 v1(170.84,110.68)
  BOTTOM w0.254: PR1714.1 170.88,110.72 v1(170.84,110.68) 169.87,109.72 PR1711.2
P3V3_STBY: length 309.7
  TOP w0.203: v1(114.43,26.68) 114.96,26.68 115.57,27.29 PR10152.1
  TOP w0.254: v1(114.4,16.34) 114.35,16.4 PR10154.1 ; D1.A 98.44,2.07 v1(97.38,2.07) ; U2.1 v1(93.82,102.56)
  TOP w0.356: R122.1 R120.1 R118.1
  TOP w0.381: R93.1 84.62,106.07 v1(85.6,105.09) ; R64.1 114.86,2.33 v1(114.86,2.38) 114.91,2.43 C115.1 ; R109.1 v1(84.47,104.15) ; v1(115.04,109.74) C34.1 115.04,108.99 U1.24 ; R62.1 v1(36.55,109.95) ; R101.1 R102.1 33.38,106.92 v1(32.77,107.53) ; R63.1 67.31,4.84 67.56,4.59 67.56,4 U22.5 68.98,3.87 C114.1 68.99,4.54 v1(69.06,4.61) ; U13.8 172.25,86.58 C28.1 ; R95.1 84.67,108.87 v1(85.22,108.32) 84.75,107.85 R94.1 ; U21.5 30.82,109.47 30.58,109.23 C26.1 v1(29.99,110) ; v1(73.68,105.19) C33.1 74.57,105.34 U14.16 ; R104.1 69.69,112.32 v1(69.08,112.32) ; PR10153.1 118.47,24.32 v1(118.82,23.97) ; v1(85.19,110.3) 85.16,110.27 R96.1 ; v1(21.46,93.99) 21.59,94.12 R110.1 ; U12.5 145.37,32.4 C16.1 v1(144.42,33.12) ; R103.1 v1(69.98,109.77) ; R105.1 v1(110.62,98.31) ; v1(154.48,15.38) 154.48,14.5 PR705.1 ; R106.1 v1(110.44,99.84) ; v1(151.64,93.87) 154.13,93.87 156.54,91.45 160.15,91.45 160.52,91.83 C36.1 ; R188.1 v1(10.13,93.92)
  TOP w0.508: v1(178.79,85.02) R60.1 172.7,85.76 172.08,86.38 C28.1 ; 174.12,32.53 173.74,32.91 PR27.1 ; v1(4.7,14.37) 4.7,13.1 4.43,12.82 L33.2 ; R122.1 175.3,94.77 v1(177.19,96.66) ; U3.8 C36.1 ; R59.1 v1(183.75,89.31)
  BOTTOM w0.254: U8.5 v1(139.09,92.23) 139.09,91.59 C101.1 ; v1(139.73,89.75) 139.78,89.7 141.25,89.7 141.5,89.95 C103.1 141.43,90.51 U9.5 ; v1(117.73,15.38) 117.86,15.25 117.86,9.41 117.04,8.6 117.04,6.17 114.39,3.51 110.31,3.51 109.58,2.79 109.58,1.54 109.25,1.21 98.12,1.21 97.51,1.82 v1(97.38,2.07) ; v1(143.05,21.12) 142.95,21.22 U4.5 141.6,21.22 141.08,20.7 C97.1 ; U7.5 131.49,48.43 C100.1 ; R38.1 136.02,88.03 140.28,88.03 v1(140.74,88.48) ; U5.5 141.66,18.89 141.99,18.56 141.99,17.79 141.62,17.43 C99.1 142.6,17.16 v1(142.62,17.18) ; U10.5 182.75,79.9 v1(183.01,79.64)
  BOTTOM w0.305: U11.5 184.22,82.74 C104.1 v1(184.66,83.07) ; U7.5 133.32,48.43 133.35,48.4 ; U6.5 134.39,50.69 133.86,50.16 C98.1
  BOTTOM w0.381: v1(148.74,15.46) 148.74,15.13 R7.1 ; v1(118.82,23.97) 117.65,23.97 116.59,25.03 115.06,25.03 114.43,25.67 v1(114.43,26.68) ; R83.1 v1(106.53,110.65) 107.28,111.39 R79.1 ; R87.1 112.78,109.36 v1(112.39,109.74) ; R108.1 R107.1 103.5,107.2 v1(102.87,107.84) ; v1(118.36,15.38) 118.49,15.25 118.49,9.29 117.63,8.42 117.63,5.86 116.05,4.28 116.05,3.29 115.16,2.4 114.88,2.4 v1(114.86,2.38) 114.88,2.35 114.88,1.69 114.72,1.52 U23.5 113.47,1.52 112.65,0.7 75.39,0.7 71.48,4.61 v1(69.06,4.61) ; R185.1 102.74,105.04 v1(102.23,104.54) ; R39.1 v1(187.85,78.77) 188.47,79.39 188.47,82.39 R10.1 ; R168.1 118.51,33.69 118.11,33.29 118.11,31.7 118.81,31 119.84,31 U19.8 119.85,30.33 119.25,29.73 C61.1 v1(118.89,28.34) ; R9.1 141.22,87.77 141.22,88 v1(140.74,88.48) ; R112.1 R111.1 110.11,100.47 v1(109.86,100.22) ; R37.1 128.83,53.99 128.22,53.38 128.22,51.17 127.59,50.54 125.94,50.54 125.35,49.95 R8.1 124.81,49.18 124.23,48.6 124.23,45.63 125.27,44.59 v1(139.95,44.59) ; R24.2 v1(187.68,76.6) ; R77.1 v1(71.75,103.65) ; v1(79.01,102.99) R81.1 R85.1 ; v1(79.32,105.56) 79.51,105.56 80.28,106.33 R100.1 R99.1 ; v1(80.47,110.76) 80.28,110.57 R97.1 R98.1 ; v1(137.92,22.24) 137.92,22.6 R36.1 ; C35.1 93.65,102.73 v1(93.82,102.56) ; R25.1 133.24,47.15 133.35,47.26 C98.1 ; R23.2 v1(129.67,99.07) ; v1(95.58,101.23) 95.94,101.59 R46.1 R124.1
  BOTTOM w0.457: v1(114.43,26.68) 116.08,26.68 116.71,27.32 116.71,28.84 116.39,29.17 112.92,29.17 112.6,28.84 111.46,28.84 111,29.3 R165.1
  BOTTOM w0.508: R21.2 v1(143.41,27.07) ; v1(183.01,79.64) 183.01,79.64 C102.1 ; R22.2 140.31,60.95 143.71,57.55 143.71,48.15 v1(142.94,47.37) 142.16,46.6 133.85,46.6
  vias: v1(159.77,30.75) v1(159.77,29.73) v1(159.77,28.72) v1(160.78,30.75) v1(160.78,29.73) v1(160.78,28.72)
P3V3_STBY_AGND: length 4.3
  TOP w0.254: PR706.2 158.21,17.95 v1(158.38,18.12) 158.46,18.2 PU33.4 v1(160.7,18.2)
  BOTTOM w0.216: PR712.1 158.26,18 v1(158.38,18.12)
  vias: v2(161.52,17.36)
P3V3_STBY_COMP: length 4.5
  TOP w0.254: PR710.1 156.03,18.43 v1(156.03,18.99) 157.6,18.99 PC829.1 157.73,18.88 157.91,18.7 159.42,18.7 PU33.3
P3V3_STBY_COMP_RC: length 3.4
  TOP w0.254: PR710.2 154.91,18.15 v3(154.33,18.73) 155.26,19.67 PC831.1
P3V3_STBY_EN: length 8.5
  TOP w0.216: PU33.15 160.7,20.96 160.45,21.21 159.17,21.21 158.1,22.28 v1(158.1,22.6) PC819.1 158.1,24.62 PR702.2 158.12,24.67 R200.2 R199.1
P3V3_STBY_FB: length 7.3
  TOP w0.254: PC829.2 PR716.1 157.68,20.66 PR717.1 ; PC829.2 157.78,19.68 v1(158.41,20.31) 158.49,20.31 159.1,19.7 PU33.1 ; PC829.2 157.69,19.67 PC831.2
  BOTTOM w0.254: v1(158.41,20.31) 158.29,20.18 157.89,20.18 157.25,19.55 PR712.2
P3V3_STBY_FB_RC: length 2.2
  TOP w0.254: PC842.1 156.75,22.24 v1(156.82,22.3) 157.21,22.3 157.71,21.81 PR716.2
P3V3_STBY_OUT: length 24.2
  BOTTOM w0.254: PR714.2 163.85,12.97 176.15,12.97 v2(178.44,15.25) 178.44,19.83 177.29,20.97 176.44,20.97 PC834.1
  vias: v1(173.64,21.78) v1(173.59,21.01) v1(174.31,21.78) v1(174.25,20.81) v1(174.73,25.99)
P3V3_STBY_PG_R: length 7.3
  TOP w0.216: PU33.7 159.13,16.7 158.45,16.02 158.45,15.59 PC820.1 157.13,14.77 156.92,14.98 156.92,15.46 v3(156.36,16.02) 156,15.66 PR704.2 PR705.2
P3V3_STBY_PWRGD: length 19.9
  TOP w0.216: v1(152.02,28.46) 149.1,31.38 R16.1
  TOP w0.254: PR704.1 155.2,15.96 v1(155.17,15.99)
  BOTTOM w0.216: v1(152.02,28.46) 153.16,28.46 154.23,27.4 154.23,18.89 154.51,18.61 154.51,16.65 v1(155.17,15.99)
P3V3_STBY_PWRGD_R: length 1.9
  TOP w0.216: U12.1 147.89,32.64 v1(148.46,32.06) 148.87,32.06 R16.2
P3V3_STBY_RT: length 1.9
  TOP w0.254: PU33.5 159.42,17.7 158.72,17.7 158.18,17.15 PR706.1
P3V3_STBY_S_VCC: length 9.9
  TOP w0.254: v1(157.48,15.53) 157.61,15.66 157.61,15.89 158.92,17.2 PU33.6 ; PU33.10 v1(161.2,14.98)
  TOP w0.305: PC822.1 161.2,14.51 v1(161.2,14.98)
  VCC1 w0.381: v1(161.2,14.98) 161.2,15.29 161.15,15.34 161.15,15.39 160.27,16.27 158.24,16.27 157.51,15.53 v1(157.48,15.53)
P3V3_STBY_SENSE_R: length 28.3
  TOP w0.254: v1(155.45,22.87) 155.57,22.75 155.57,22.74 155.95,22.36 PC842.2 PR717.2
  BOTTOM w0.254: v1(155.45,22.87) 155.45,24.6 158.55,27.7 175.01,27.7 176.15,26.56 PR719.1
P3V3_STBY_VIN: length 5.5
  TOP w0.254: v1(159.89,14.87) 160.24,14.87 160.7,15.33 PU33.9
  TOP w0.305: v1(159.89,14.87) 160.31,14.46 PC824.1
  BOTTOM w0.254: PR708.2 160.88,12.84 159.89,13.83 v1(159.89,14.87)
P3V3_STBY_VREF: length 2.3
  TOP w0.254: v1(158.43,19.24) 158.47,19.2 159.42,19.2 PU33.2
  BOTTOM w0.254: PC823.1 158.61,19.06 v1(158.43,19.24)
P3V3_STBY_VSNS: length 6.6
  TOP w0.254: v1(159.25,15.57) 159.95,16.28 PU33.8
  BOTTOM w0.254: PR711.2 160.31,16.63 v1(159.25,15.57) 160.19,15.57 160.58,15.18 160.58,14.59 161.18,13.98 PR714.1
P12V_FAN: length 31
  TOP w0.254: PU17.2 156.63,68.47 156.48,68.62 156.48,71.1 v1(156.59,71.21)
  BOTTOM w0.254: U18.7 179.74,74.21 178.44,74.21 C52.1 177.92,74.36 177.36,74.36 C96.2 177.02,74.31 157.25,74.31 156.51,73.57 156.51,71.28 v1(156.59,71.21)
  vias: v1(157.23,66.18) v1(157.23,65.42) v1(157.48,71.64) v1(157.48,70.88) v1(157.99,66.18) v1(157.99,65.42) v1(158.24,72.4) v1(158.24,71.64) v1(158.24,70.88) v1(158.75,66.18) v1(158.75,65.42) v1(159,72.4) v1(159,71.64) v1(159,70.88) v1(159.51,66.18) v1(159.51,65.42) v1(159.51,63.26) v1(159.64,64.28) v1(159.77,72.4) v1(159.77,71.64) v1(159.77,70.88) v1(160.32,68.52) v1(160.27,66.18) v1(160.53,72.4) v1(160.53,71.64) v1(160.53,70.88) v1(160.53,70.12) v1(160.53,69.36) v1(160.53,67.83) v1(160.53,67.07) v1(161.29,72.4) v1(161.29,71.64) v1(161.29,70.88) v1(161.29,70.12) v1(161.29,69.36) v1(161.29,68.59) v1(161.29,67.83) v1(161.29,67.07) v1(162.05,72.4) v1(162.05,71.64) v1(162.05,70.88) v1(162.05,70.12) v1(162.05,69.36) v1(162.05,68.59) v1(162.05,67.83) v1(162.05,67.07) v1(162.05,64.4) v1(162.05,63.13) v1(169.93,72.66) v1(170.94,72.66) v1(171.96,73.29) v1(172.97,73.29)
P12V_PSU: length 213.6
  TOP w0.216: v1(118.62,21.73) 117.93,21.05 PR1011.1
  TOP w0.254: PR1017.2 89.07,77.04 89.07,74.76 88.94,74.63 PU19.1 ; PU18.1 88.94,81.49 89.07,81.61 89.07,83.77 PR1018.2 ; PR1019.2 89.07,56.47 89.07,54.18 88.94,54.06 PU22.1 ; 28.66,61.57 28.55,61.57 28.15,61.17 SHORT1.2 ; PU20.1 88.94,67.77 89.07,67.9 89.07,70.18 PR1016.2 ; PU21.1 88.94,60.91 89.07,61.04 89.07,63.32 PR1015.2 ; R58.2 89.07,42.75 89.07,40.47 88.89,40.29 87.16,40.29 R189.1 ; R48.1 103.81,13.02 104.01,12.82 104.01,10.43 103.83,10.24 R154.1 ; PR1020.2 89.07,49.61 89.07,47.32 88.94,47.2 87.19,47.2
  TOP w0.381: R152.1 108.03,4.64 v1(108.58,4.08) ; PR23.1 160.99,34.05 157.99,31.05 157.99,30.06 v1(155.6,27.68) ; PR1038.1 PR1034.1 103.38,18.96 103.38,16.65 102.35,15.62 100.36,15.62
  VCC1 w0.254: 87.76,15.25 89.28,13.73 112.9,13.73 116.48,17.31 116.48,19.6 v1(118.62,21.73)
  VCC1 w0.381: v1(155.6,27.68) 154.74,26.81 149.86,26.81 149.22,26.18 130.98,26.18 130.73,25.92 122.81,25.92 121.54,24.65 121.54,22.77 118.08,19.32 118.08,17.79 111,10.71 88.42,10.71 v1(86.89,12.23)
  BOTTOM w0.216: v1(118.62,21.73) 118.49,21.86 118.49,22.52 117.74,23.27 117.22,23.27 R157.1
  BOTTOM w0.381: 102.11,11.52 101.85,11.27 101.85,7.15 102.62,6.39 103.63,6.39 105.94,4.08 v1(108.58,4.08)
  BOTTOM w0.508: 88.9,14.49 102.36,14.49 106.68,18.81 PR1039.1
  vias: v1(15.71,49.07) v1(15.71,44.87) v1(15.71,40.67) v1(15.71,36.47) v1(15.71,32.27) v1(15.71,28.07) v1(21.21,49.07) v1(21.21,44.87) v1(21.21,40.67) v1(21.21,36.47) v1(21.21,32.27) v1(21.21,28.07) v1(22.48,20.08) v1(22.61,22.62) v1(22.86,23.51) v1(23.57,20.14) v1(28.75,96.99) v1(28.75,91.48) v1(28.75,56.99) v1(28.75,51.48) v1(28.8,20.39) v1(28.8,14.87) v1(30.23,71.82) v1(30.28,78.86) v1(30.28,76.6) v1(30.28,69.43) v1(30.35,68.47) v1(30.71,66.79) v1(30.71,65.06) v1(31.37,78.86) v1(31.42,76.6) v1(31.47,71.82) v1(31.55,69.48) v1(32.95,96.99) v1(32.95,91.48) v1(32.95,56.99) v1(32.95,51.48) v1(33,20.39) v1(33,14.87) v1(37.15,96.99) v1(37.15,91.48) v1(37.15,56.99) v1(37.15,51.48) v1(37.2,20.39) v1(37.2,14.87) v1(41.35,96.99) v1(41.35,91.48) v1(41.35,56.99) v1(41.35,51.48) v1(41.4,20.39) v1(41.4,14.87) v1(44.63,27.55) v1(44.78,25.11) v1(45.55,96.99) v1(45.55,91.48) v1(45.55,56.99) v1(45.55,51.48) v1(45.6,20.39) v1(45.6,14.87) v1(45.82,27.55) v1(45.97,25.11) v1(49.75,96.99) v1(49.75,91.48) v1(49.75,56.99) v1(49.75,51.48) v1(49.8,20.39) v1(49.8,14.87) v1(56.46,66.84) v1(56.59,64.4) v1(57.53,66.82) v1(57.56,64.43) v1(58.37,48.3) v1(58.5,45.86) v1(59.44,48.27) v1(59.46,45.89) v1(60.3,84.11) v1(60.3,82.92) v1(60.66,66.84) v1(60.78,64.4) v1(61.72,66.82) v1(61.75,64.43) v1(62.13,37.17) v1(62.74,84.27) v1(62.74,83.07) v1(65.74,37.15) v1(67.69,43.7) v1(67.67,36.9) v1(69.47,43.7) v1(70.02,84.19) v1(70.02,83) v1(72.34,84.27) v1(72.34,83.07) v1(75.59,84.44) v1(77.17,64.28) v1(77.34,66.82) v1(77.55,48.17) v1(77.6,84.52) v1(77.67,45.73) v1(78.13,64.3) v1(78.49,66.82) v1(78.61,48.15) v1(78.64,45.76) v1(79.5,84.72) v1(80.54,84.85) v1(81.84,14.82) v1(81.86,13.58) v1(84.2,14.87) v1(84.28,13.5) v1(84.4,79.21) v1(84.4,78.45) v1(84.4,77.69) v1(84.4,76.93) v1(84.4,72.35) v1(84.4,71.59) v1(84.4,70.83) v1(84.4,70.07) v1(84.4,65.5) v1(84.4,64.73) v1(84.4,63.97) v1(84.4,63.21) v1(84.4,58.64) v1(84.4,57.88) v1(84.4,57.11) v1(84.4,56.35) v1(84.4,51.78) v1(84.4,51.02) v1(84.4,50.26) v1(84.4,49.49) v1(84.4,44.92) v1(84.4,44.16) v1(84.4,43.4) v1(84.4,42.64) v1(84.51,37.99) v1(84.51,37.15) v1(85.42,79.21) v1(85.42,78.45) v1(85.42,77.69) v1(85.42,76.93) v1(85.42,72.35) v1(85.42,71.59) v1(85.42,70.83) v1(85.42,70.07) v1(85.42,65.5) v1(85.42,64.73) v1(85.42,63.97) v1(85.42,63.21) v1(85.42,58.64) v1(85.42,57.88) v1(85.42,57.11) v1(85.42,56.35) v1(85.42,51.78) v1(85.42,51.02) v1(85.42,50.26) v1(85.42,49.49) v1(85.42,44.92) v1(85.42,44.16) v1(85.42,43.4) v1(85.42,42.64) v1(85.37,16.04) v1(85.37,15.28) v1(85.37,14.52) v1(85.37,13.76) v1(85.37,12.99) v1(85.37,12.23) v1(85.52,37.99) v1(85.52,37.15) v1(86.13,16.04) v1(86.13,15.28) v1(86.13,14.52) v1(86.13,13.76) v1(86.13,12.99) v1(86.13,12.23) v1(86.44,79.21) v1(86.44,78.45) v1(86.44,77.69) v1(86.44,76.93) v1(86.44,72.35) v1(86.44,71.59) v1(86.44,70.83) v1(86.44,70.07) v1(86.44,65.5) v1(86.44,64.73) v1(86.44,63.97) v1(86.44,63.21) v1(86.44,58.64) v1(86.44,57.88) v1(86.44,57.11) v1(86.44,56.35) v1(86.44,51.78) v1(86.44,51.02) v1(86.44,50.26) v1(86.44,49.49) v1(86.44,44.92) v1(86.44,44.16) v1(86.44,43.4) v1(86.44,42.64) v1(86.54,37.99) v1(86.54,37.15) v1(86.89,16.04) v1(86.89,15.28) v1(86.89,14.52) v1(86.89,13.76) v1(86.89,12.99) v1(87.45,79.21) v1(87.45,78.45) v1(87.45,77.69) v1(87.45,76.93) v1(87.45,72.35) v1(87.45,71.59) v1(87.45,70.83) v1(87.45,70.07) v1(87.45,65.5) v1(87.45,64.73) v1(87.45,63.97) v1(87.45,63.21) v1(87.45,58.64) v1(87.45,57.88) v1(87.45,57.11) v1(87.45,56.35) v1(87.45,51.78) v1(87.45,51.02) v1(87.45,50.26) v1(87.45,49.49) v1(87.45,44.92) v1(87.45,44.16) v1(87.45,43.4) v1(87.45,42.64) v1(87.55,37.99) v1(87.55,37.15)
P12V_RISER3: length 10.2
  TOP w0.254: R204.1 135.09,24.59 132.74,24.59 132.59,24.44 PU10.2 ; v1(130.34,24.33) 130.08,24.59 128.17,24.59 128.02,24.44 PU11.2
  BOTTOM w0.254: v1(130.34,24.33) 130.6,24.59 131.31,24.59 R205.1
  vias: v1(123.62,12.33) v1(123.67,11.37) v1(123.83,13.35) v1(124.61,12.31) v1(124.69,11.37) v1(124.84,13.35) v1(125.7,12.31) v1(125.7,11.37) v1(125.98,13.35) v1(126.36,19.95) v1(126.36,18.94) v1(126.36,17.92) v1(126.36,16.91) v1(126.36,15.89) v1(127.38,19.95) v1(127.38,18.94) v1(127.38,17.92) v1(127.38,16.91) v1(127.38,15.89) v1(128.4,19.95) v1(128.4,18.94) v1(128.4,17.92) v1(128.4,16.91) v1(128.4,15.89) v1(129.41,19.95) v1(129.41,18.94) v1(129.41,17.92) v1(129.41,16.91) v1(129.41,15.89) v1(130.3,22.62) v1(130.3,21.6) v1(130.43,19.95) v1(130.43,18.94) v1(130.43,17.92) v1(130.43,16.91) v1(130.43,15.89) v1(131.44,19.95) v1(131.44,18.94) v1(131.44,17.92) v1(131.44,16.91) v1(131.44,15.89) v1(133.99,15.64) v1(137.95,20.13) v1(137.95,19.17) v1(137.87,15.03) v1(137.97,21.2) v1(138,18.07) v1(138.2,16.25) v1(138.86,15.03) v1(139.83,13.68) v1(140.94,13.68)
